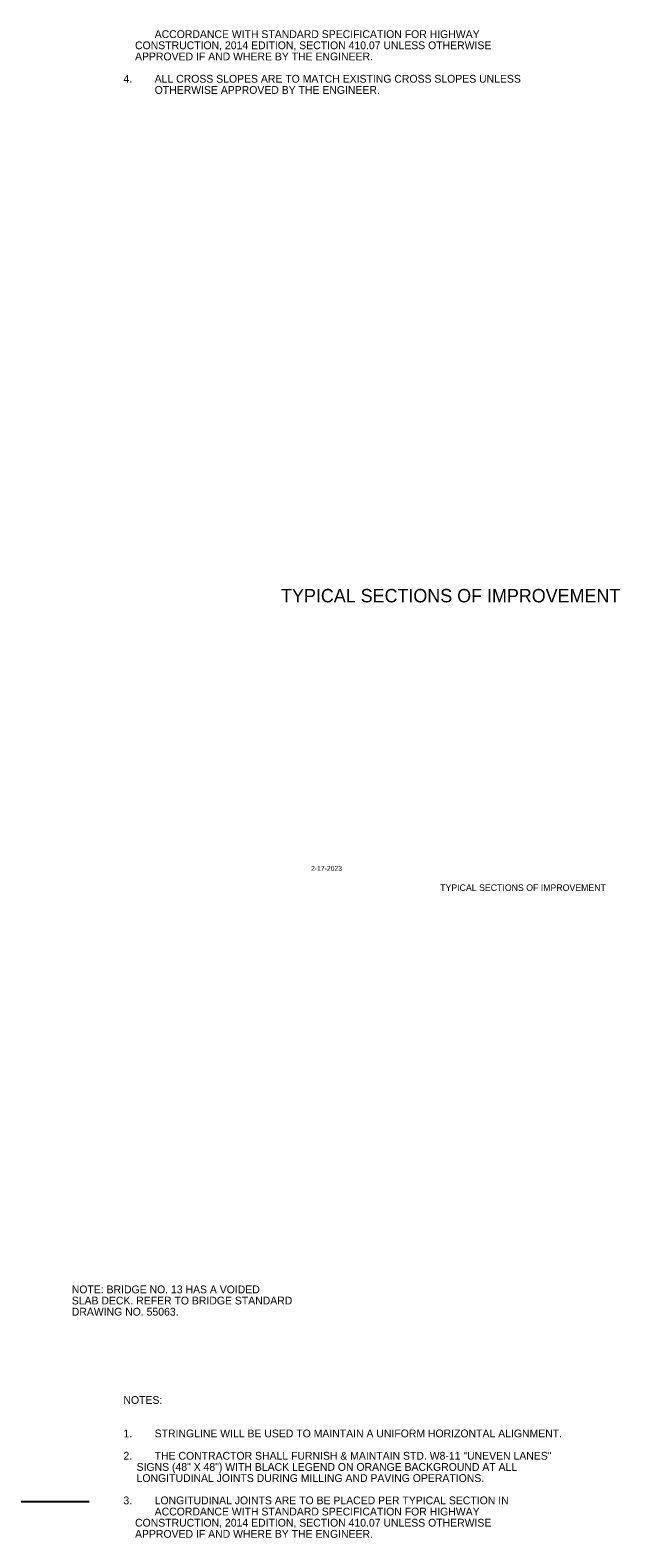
# Model space of a CAD drawing. Extents: x 549600 to 1930787, y -1955432 to 596640.
# Drawn here: x 552017 to 552546, y -1951270 to -1949919 of the extents above; entities that cross this region are included whole.
import ezdxf

# ---------------------------------------------------------------- set-up
doc = ezdxf.new("R2010")
doc.units = 0
for name, color, linetype in [('R_Border', 7, 'Continuous'), ('R_Border Notes', 7, 'Continuous'), ('R_Border Prem', 7, 'Continuous')]:
    doc.layers.add(name, color=color, linetype=linetype)

msp = doc.modelspace()

# ---------------------------------------------------------------- linework, layer by layer
at = {"layer": 'R_Border'}
msp.add_line((551009, -1951237.9), (552070.2, -1951237.9), dxfattribs=at)

# ---------------------------------------------------------------- texts
msp.add_text('TYPICAL SECTIONS OF IMPROVEMENT', height=12, rotation=360, dxfattribs=at).set_placement((552242.3, -1950432.1))
at = {"layer": 'R_Border Notes'}
for s, p in [('    CONSTRUCTION, 2014 EDITION, SECTION 410.07 UNLESS OTHERWISE', (552101, -1949936.4)), ('ACCORDANCE WITH STANDARD SPECIFICATION FOR HIGHWAY', (552129, -1949926.4)), ('    APPROVED IF AND WHERE BY THE ENGINEER.', (552101, -1949946.4)), ('4.', (552101, -1949966.4)), ('ALL CROSS SLOPES ARE TO MATCH EXISTING CROSS SLOPES UNLESS ', (552129, -1949966.4)), ('OTHERWISE APPROVED BY THE ENGINEER.', (552129, -1949976.4)), ('NOTE: BRIDGE NO. 13 HAS A VOIDED', (552054.7, -1951051.3)), ('SLAB DECK. REFER TO BRIDGE STANDARD', (552054.7, -1951061.3)), ('DRAWING NO. 55063.', (552054.7, -1951071.3)), ('NOTES: ', (552101, -1951150.4)), ('1.', (552101, -1951180.4)), ('STRINGLINE WILL BE USED TO MAINTAIN A UNIFORM HORIZONTAL ALIGNMENT.', (552129, -1951180.4)), ('2.', (552101, -1951200.4)), ('THE CONTRACTOR SHALL FURNISH & MAINTAIN STD. W8-11 "UNEVEN LANES" ', (552129, -1951200.4)), ('    SIGNS (48" X 48") WITH BLACK LEGEND ON ORANGE BACKGROUND AT ALL ', (552102.4, -1951210.4)), ('    LONGITUDINAL JOINTS DURING MILLING AND PAVING OPERATIONS.', (552102.4, -1951220.4)), ('3.', (552101, -1951240.4)), ('LONGITUDINAL JOINTS ARE TO BE PLACED PER TYPICAL SECTION IN ', (552129, -1951240.4)), ('    CONSTRUCTION, 2014 EDITION, SECTION 410.07 UNLESS OTHERWISE', (552101, -1951260.4)), ('ACCORDANCE WITH STANDARD SPECIFICATION FOR HIGHWAY', (552129, -1951250.4)), ('    APPROVED IF AND WHERE BY THE ENGINEER.', (552101, -1951270.4))]:
    msp.add_text(s, height=7, dxfattribs=at).set_placement(p)
at = {"layer": 'R_Border Prem'}
msp.add_text('2-17-2023', height=4.4, dxfattribs=at).set_placement((552269.2, -1950672.7))
msp.add_text('TYPICAL SECTIONS OF IMPROVEMENT', height=5.862, rotation=360, dxfattribs=at).set_placement((552384.9, -1950690.7))

doc.saveas('drawing.dxf')
